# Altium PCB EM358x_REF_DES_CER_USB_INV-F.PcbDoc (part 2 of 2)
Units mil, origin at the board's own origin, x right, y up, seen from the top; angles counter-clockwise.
Board outline 2135 x 955 mil, 4 copper layers (Top Layer, Gnd Layer 2, Power Layer 3, Bottom Layer), stack 61.6 mil thick; 69 components, 52 nets, 241 pads, 167 vias.
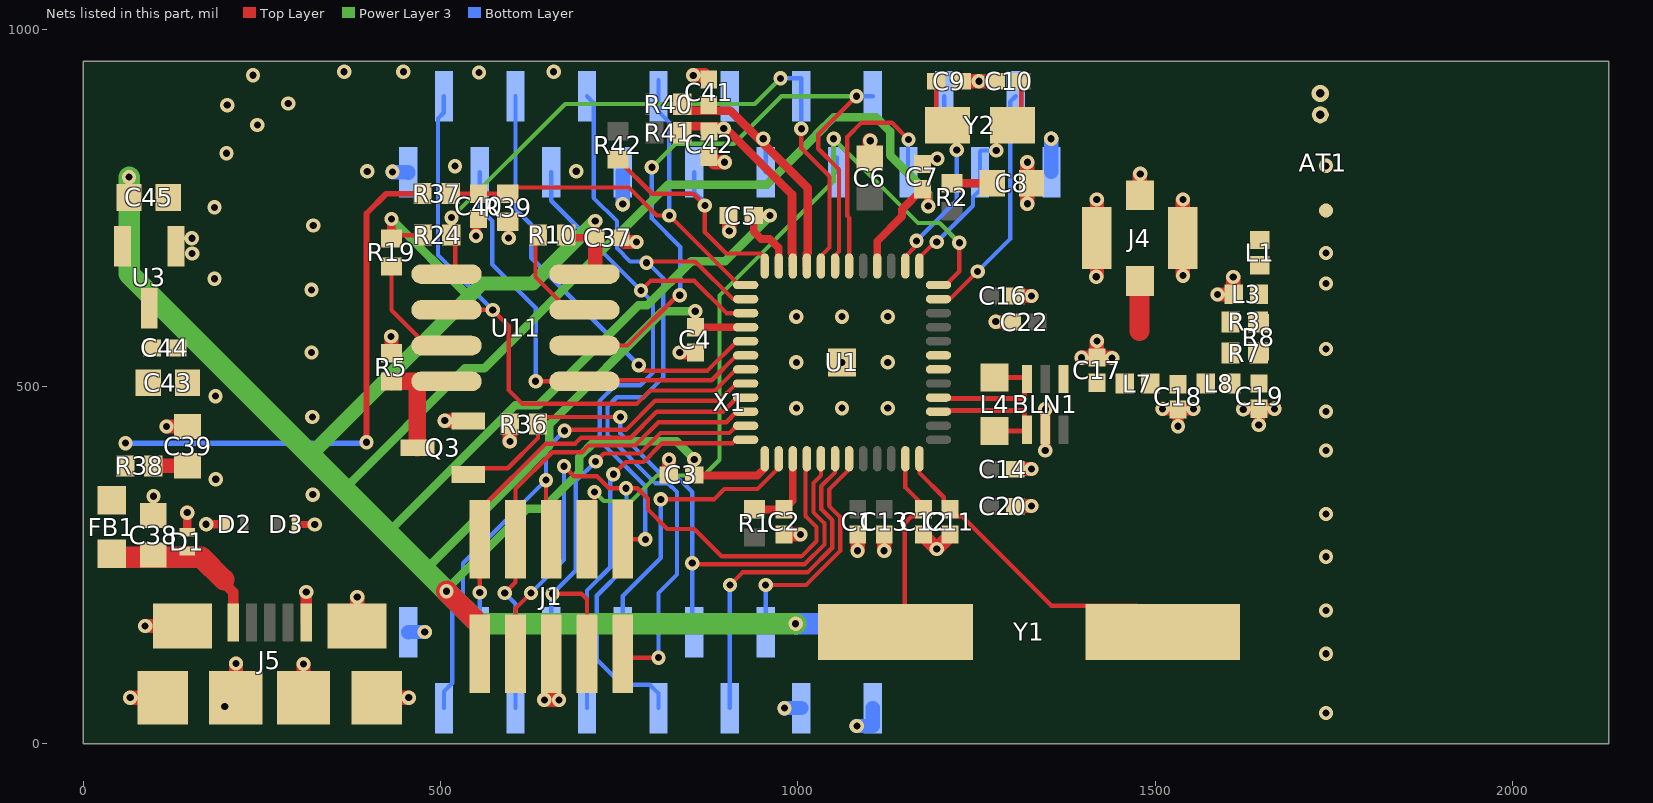
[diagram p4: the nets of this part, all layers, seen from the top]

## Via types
v1: diameter 20, hole 10, Top Layer to Bottom Layer, 166 vias
v2: diameter 24, hole 12, Top Layer to Bottom Layer, 1 vias

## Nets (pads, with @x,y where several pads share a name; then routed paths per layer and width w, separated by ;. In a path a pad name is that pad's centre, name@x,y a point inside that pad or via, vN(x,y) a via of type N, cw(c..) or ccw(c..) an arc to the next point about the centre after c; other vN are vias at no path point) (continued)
GND: AT1.2 BLN1.5 C1.2 C2.2 C3.2 C4.2 C5.2 C6.2 C7.2 C8.2 C9.2 C10.2 C11.2 C12.2 C13.2 C14.2 C16.2 C17.2 C18.2 C19.2 C20.2 C22.2 C37.2 C38.2 C39.2 C40.2 C41.2 C42.2 C43.2 C44.2 C45.2 D1.1 D2.1 D3.1 J1.5 J4.2 J4.3 J4.4 J5.5 J5.6 J5.7 J5.8 J5.9 J5.10 J5.11 L3.2 Q3.2 R5.2 R36.2 R39.2 U1.49 U3.1 X1.1 X1.13 X1.19 X1.20 X1.31 X1.33 | length 1925.6
  Top Layer w10: D3.1@296.79,306.79 296.88,306.7 v1(324.16,306.7)
  Top Layer w12: D1.1@145.63,295.5 v1(145.63,323.2) ; v1(172.03,306.92) D2.1@198.5,306.92 ; v1(549.77,710.4) 549.77,730.42 C40.2@553.4,734.05 ; R39.2@594.1,730.21 595.42,728.89 v1(595.42,707.43)
  Top Layer w14: v1@1347,468 v1(1346.5,468) 1346.41,467.91 BLN1.5@1346.41,439.13 v1(1346.41,410.09) v1@1347.5,409
  Top Layer w16: v1@312.21,213.89 v1(312.21,212.19) v1(312.21,212.19) J5.5@312.25,169.61 ; v1(1510.5,468.3) 1511.34,467.46 C18.2@1532.1,467.46 ; v1(1532.2,444.2) 1532.1,444.3 C18.2@1532.1,467.46 ; v1(1553.9,468.3) 1553.06,467.46 C18.2@1532.1,467.46 ; v1@1624.26,468.46 C19.2@1645.6,468.46 ; v1@1644.4,446.6 v1(1645.2,445.8) 1645.6,446.2 C19.2@1645.6,468.46 ; v1(1667.1,468.5) C19.2@1645.6,468.46
  Top Layer w20: v1(65.81,64.29) J5.10@111.46,64.29 ; v1(86.7,164.68) J5.11@139.02,164.68 ; v1(116.59,443.76) 116.71,443.88 C39.2@146.07,443.88 ; v1@145.41,323.42 v1(145.63,323.2) ; J5.9@213.82,64.29 v1(213.82,111.98) ; J5.8@308.31,64.29 v1(308.31,111.39) ; J5.6@383.11,164.68 383.45,165.02 v1(383.45,205.17) ; J5.7@410.67,64.29 v1(455.71,64.29) ; v1(431,569.8) 431.4,569.4 R5.2@431.4,546.07 ; v1(506,452) 538.33,452 Q3.2@538.83,451.5 ; v1(597.1,422.9) R36.2@597.1,446.9 ; J1.5@655,126 655,61.44 v1@655.26,61.18 ; v1(665.82,60.96) 665.6,61.18 v1@655.26,61.18 ; C37.2@752.06,707.87 757.89,702.04 v1(774.39,702.04) ; C3.2@819.5,376.06 C3.2@819.56,376 819.8,376.24 v1(819.8,397.7) ; v1(834.8,547.3) v1(834.8,547.3) C4.2@856.8,547.26 ; v1(853.81,935.13) 869.61,935.13 C41.2@875.5,929.24 ; C42.2@876,821.06 883.59,813.47 v1(897.7,813.47) ; C5.2@902.96,738.9 904.19,737.67 v1(904.19,717.11) ; C2.2@981,292.56 v1(1003.8,292.6) v1(1003.8,292.6) ; v1@1084,270.2 C1.2@1084,292.56 ; C6.2@1100.6,819.12 1100.6,844.3 1101.2,843.7 v1(1101.4,843.7) ; v1(1120.9,269.8) 1121,269.9 C13.2@1121,292.56 ; C12.2@1176,292.56 1176,290.8 v1(1194.4,272.4) 1213,291 C11.2@1213,292.56 ; C9.2@1229.43,926.94 v1(1253.43,926.94) C10.2@1277.43,926.94 ; v1(1277,590.5) 1277.5,590 C22.2@1299.56,590 ; C20.2@1304.44,332 1304.84,332.4 v1(1326.9,332.4) ; C16.2@1304.44,626.5 v1(1327,626.5) ; C14.2@1304.64,384.2 v1(1326.9,384.2) ; v1(1321.3,755.4) C8.2@1321.3,778.18 ; v1(1321.3,813.5) C8.2@1321.3,778.18 ; C8.2@1327.12,784 C8.2@1321.3,778.18 ; v1@1397.44,540.34 C17.2@1418.5,540.34 ; v1@1418.5,563 C17.2@1418.5,540.34 ; v1@1418.66,654.36 J4.3@1418.66,707.4 v1@1418.66,761.34 ; v1@1439.06,540.34 C17.2@1418.5,540.34 ; J4.4@1478.7,767.44 v1@1478.7,796.8 ; v1(1510.5,468.3) v1@1510.66,468.46 ; v1@1538.74,655.36 J4.2@1538.74,707.4 v1@1538.74,761.04 ; J4.2@1539.8,688.6 1548.9,697.7 J4.2@1548.86,697.74 ; v1(1587.3,628.4) 1608.68,628.4 1609.4,629.12 v1(1609.4,652.9) ; L3.2@1607.7,627.42 1608.76,626.36 1609.76,626.36 L3.2@1609.76,626.56 ; L3.2@1609.56,626.76 L3.2@1609.76,626.56 ; L3.2@1609.96,626.36 L3.2@1609.76,626.56 ; v1(1667.1,468.5) v1(1667.1,468.5) ; v1@655.26,61.18 655.48,60.96 645.58,60.96 v1(645.36,61.18) v1@655.26,61.18
  Bottom Layer w20: v1(432.73,800.16) 433.19,799.7 X1.19@455,799.7 454.6,799.3 X1.19@455.06,798.84 ; X1.20@455,156 455.33,156.33 v1(478.05,156.33) ; v1(755,754.9) X1.13@755,799.7 ; v1(981.52,49.63) 981.59,49.7 X1.31@1005,49.7 ; v1(1082.72,24.77) 1104.83,24.77 1105,24.94 X1.33@1105,49.7 ; X1.1@1354.6,800.1 v1(1354.6,846.5)
  other v1: 1739.2,42.9 198.1,52 1739.2,125.8 1739.2,186.2 1739.2,261.4 1083.6,269.8 1739.2,321.3 98.4,346.2 321.3,348.4 185.5,370 1739.2,410.2 320.7,457.1 1739.2,464.7 1623.5,467.7 997.98,469.48 1062,469.48 1126.02,469.48 185.2,486.3 997.98,533.5 1062,533.5 1126.02,533.5 1397,539.9 1439.9,539.5 319.5,547.2 1739.2,552.3 1418.8,563.3 997.98,597.52 1062,597.52 1126.02,597.52 319.5,635 1739.2,644 183.7,650.6 1417.6,653.3 1539.2,654.9 152.45,685.98 1739.2,686.5 152.12,707.21 321.9,725.1 183.7,750.4 1418.5,761.5 1539.2,761.5 1479.2,797.3 397.6,800.8 690,801 520.2,808.1 1739.2,808.5 1195.14,818.42 200.5,826.1 243.8,865.7 201.7,893.5 287,895.8 237.7,935.4 553.9,939.1 365.2,940.3 448.1,940.3 658.4,940.3
  other v2: 1731.2,910
JCLK: J1.6 U1.32 X1.21 | length 825
  Top Layer w6: v1(647.67,368.74) 647.67,293.33 J1.6@655,286 ; v1(673.52,437.82) 674.73,439.03 759.72,439.03 800.39,479.7 889.8,479.7 914.07,503.97 U1.32@927.16,503.97
  Bottom Layer w6: X1.21@505,49.7 505,73.06 516.61,84.66 516.33,84.94 516.33,188.78 531.4,203.85 531.4,252.47 v1(647.67,368.74) 647.67,411.97 v1(673.52,437.82)
NetAT1_1: AT1.1 L1.2
NetBLN1_1: BLN1.1 C17.1 L7.1
NetC2_1: C2.1 R1.2 U1.39 | length 117.1
  Top Layer w11: R1.2@939.7,327.77 980.77,327.77 C2.1@981,328 993,340 993,398.56 U1.39@993.1,398.66
NetC8_1: C8.1 R2.2 | length 56.2
  Top Layer w12: R2.2@1216,784.37 1271.63,784.37 C8.1@1272,784
NetC18_1: C18.1 L7.2 L8.1
NetC19_1: C19.1 L8.2 R7.1 R8.1
NetC38_1: C38.1 D1.2 FB1.1 J5.1 | length 211.8
  Top Layer w15: 194.81,226.79 209.88,211.72 J5.1@209.88,169.61
  Top Layer w30: 61.85,260.79 165.24,260.79 197.03,229.01
NetC39_1: C39.1 R38.1 | length 48
  Top Layer w20: R38.1@98.11,388.76 C39.1@146.07,388.76
NetJ4_1: J4.1 R3.2 R7.2 | length 70
  Top Layer w28: 1477.9,577.4 J4.1@1477.9,647.36
NetL1_1: L1.1 L3.1 R3.1 R8.2
NRESET: J1.8 U1.12 X1.7 | length 1164.9
  Top Layer w6: J1.8@705,286 715.54,296.54 v1(715.54,352.24) ; U1.12@1196.84,641.77 1207.07,641.77 1226.1,660.8 v1(1226.1,701)
  Power Layer 3 w6: v1(715.54,352.24) 728.37,339.41 767.22,339.41 803.01,375.2 868.36,375.2 890.5,397.34 890.5,627.19 1050.2,786.89 v1(1050.2,846.5) 1168.2,728.5 1198.6,728.5 v1(1226.1,701)
  Bottom Layer w6: v1(1050.2,846.5) 1049.2,845.5 1049.2,814.4 1055,820.2 X1.7@1055,799.7
NSF_GND: Q3.3 R5.1 U11.4 | length 170.2
  Top Layer w25: R5.1@431.4,506.7 431.7,507 U11.4@508.54,507 ; Q3.3@467.57,414.1 U11.4@467.57,507
NSF_HOLD: R10.1 U11.7 | length 169.7
  Top Layer w6: R10.1@627.13,714.11 R10.1@627.13,723 ; R10.1@633,713.05 R10.1@634.06,714.11 ; R10.1@636.57,711.94 633,708.37 633,653.15 679.15,607 U11.7@712.96,607
NSF_WP: R19.1 U11.3 | length 170.3
  Top Layer w6: R19.1@431.4,667.63 431.4,606.5 480.9,557 U11.3@520.04,557
OSCA: C11.1 U1.48 Y1.1 | length 458.7
  Top Layer w6: U1.48@1170.27,398.66 1170.27,378.73 1204.2,344.8 1204.2,336.8 C11.1@1213,328 1213.7,327.3 1218.4,327.3 1218.4,324.76 1224.95,318.2 1229.64,318.2 1354.77,193.07 1474,193.07 Y1.1@1510.74,156.33
OSCB: C12.1 U1.47 Y1.2 | length 277.3
  Top Layer w6: Y1.2@1136.72,156.33 1149.6,169.21 1149.6,308.44 1159.36,318.2 1163.5,318.2 C12.1@1173.5,328.2 ; U1.47@1150.58,398.66 1150.58,358.52 C12.1@1176,333.1 ; C12.1@1167.9,328.2 C12.1@1173.5,328.2 ; C12.1@1176,328 1175.8,328.2 C12.1@1173.5,328.2 ; C12.1@1176,330.7 C12.1@1173.5,328.2
PA01_D_N: C41.1 R40.2 U1.21 X1.9 | length 398.8
  Top Layer w12: R40.2@838.37,894.75 838.37,885.76 875.5,885.76 905.71,885.76 948.34,843.14 v1@948.59,842.89 ; v1(951.7,846.5) 951.7,846 v1@948.59,842.89 ; U1.21@1012.79,668.34 1012.79,685.79 1013.9,686.9 1013.9,777.58 v1@948.59,842.89
  Top Layer w18: R40.2@838.37,895.37 R40.2@839.63,895.37 ; C41.1@875.5,891.7 C41.1@875.5,893.8
  Bottom Layer w6: v1(951.7,846.5) 956,846.5 955,845.5 X1.9@955,799.7
PA01_D_P: C42.1 R41.2 U1.22 X1.10 | length 300.6
  Top Layer w12: R41.2@838.37,854.78 847.36,863.76 876,863.76 896.5,863.76 896.6,863.76 898.13,862.23 v1@899.76,860.6 ; v1(896.5,860.6) v1@899.76,860.6 ; U1.22@993.1,668.34 993.1,685.5 991.9,686.7 991.9,768.47 v1@899.76,860.6
PA2: R42.2 U1.24 X1.11 | length 348.8
  Top Layer w6: R42.2@748.21,817.44 796.29,769.36 853.64,769.36 v1(870,753) 870,715.66 899.86,685.8 947.8,685.8 953.73,679.87 U1.24@953.73,668.34
  Bottom Layer w6: X1.11@855,799.7 855,772 870,757 v1(870,753)
PA3: C40.1 R37.2 R39.1 U1.25 X1.12 | length 668.4
  Top Layer w6: R37.2@514.34,769.58 514.43,769.49 C40.1@553.4,769.49 594.01,769.49 R39.1@594.1,769.58 602.71,778.19 763.69,778.19 802.78,739.1 v1(820.3,739.1) 917.63,641.77 U1.25@927.16,641.77
  Bottom Layer w6: X1.12@805,928.16 X1.12@805,906 805,884.39 820.3,869.09 v1(820.3,739.1)
PA4: J1.9 U1.26 X1.14 | length 1162.8
  Top Layer w6: J1.9@755,114.5 760.8,120.3 v1(805.1,120.3) ; v1(788.25,673) 788.25,674.75 788.2,674.8 856.6,674.8 909.32,622.08 U1.26@914.42,622.08
  Bottom Layer w6: X1.14@705,906 714.33,896.67 714.33,763.75 746.89,731.19 746.89,693.35 765.44,674.8 v1@788.2,674.8 ; v1(788.25,673) 788.25,674.75 v1@788.2,674.8 ; v1(805.1,120.3) 805.1,210.8 830.93,236.63 830.93,352.13 818.86,364.2 801.04,364.2 733.73,431.51 733.73,471.53 746.8,484.6 784,484.6 811.6,512.2 811.6,651.4 v1@788.2,674.8
PA5: J1.10 U1.27 X1.15 | length 853.4
  Top Layer w6: J1.10@755,286 755.2,285.8 v1(786.71,285.8) ; v1(780.5,634.2) 793.9,647.6 855.1,647.6 900.3,602.4 U1.27@927.16,602.4
  Bottom Layer w6: X1.15@655,799.7 655,759.7 v1(780.5,634.2) 797.5,617.2 797.5,519.3 779.7,501.5 745,501.5 722.73,479.23 722.73,424.14 786.71,360.16 v1(786.71,285.8)
PA6: U1.29 X1.16 | length 617.7
  Top Layer w6: v1(777.4,529.6) 785.03,521.97 873.79,521.97 914.85,563.03 U1.29@927.16,563.03
  Bottom Layer w6: X1.16@605,906 605,748.12 627.13,725.99 627.13,679.87 v1(777.4,529.6)
PA7: U1.18 X1.5 | length 331
  Top Layer w6: U1.18@1071.84,668.34 1072,668.5 1072,735.6 1069.4,738.2 1069.4,849.32 1089.08,869 1131.5,869 v1(1155.1,845.4)
  Bottom Layer w6: X1.5@1154.2,800.5 1154.2,844.5 v1(1155.1,845.4)
PB0: U1.36 X1.25 | length 573.9
  Top Layer w6: v1(741.94,376.88) 759.21,394.15 784.03,394.15 810.18,420.3 908.6,420.3 913.53,425.23 U1.36@927.16,425.23 ; 785.3,395.1 803.8,413.6
  Bottom Layer w6: X1.25@705,49.7 705,214.21 737.63,246.84 737.63,372.57 v1(741.94,376.88)
PB1: U1.30 U11.5 X1.17 | length 634.1
  Top Layer w6: v1(633.2,507) U11.5@701.46,507 703.06,508.6 879.6,508.6 914.34,543.34 U1.30@927.16,543.34
  Bottom Layer w6: X1.17@555,799.7 555,748.84 572.54,731.3 572.54,670.66 633.2,610 v1(633.2,507)
PB2: U1.31 U11.2 X1.18 | length 880.1
  Top Layer w6: U11.2@508.54,607 573.1,607 v1(573.2,606.9) 595.4,584.7 595.4,494.9 614.9,475.4 774.5,475.4 793.2,494.1 884,494.1 913.56,523.66 U1.31@927.16,523.66
  Bottom Layer w6: X1.18@505,906 504.5,905.5 504.5,882.8 496.5,874.8 496.5,683.6 v1(573.2,606.9)
PB3: U1.19 U11.6 X1.6 | length 982.8
  Top Layer w6: U11.6@701.46,557 761.6,557 832.1,627.5 v1(834.9,627.5) ; U1.19@1052.16,668.34 1052.16,683.16 1057.6,688.6 1057.6,803.6 1028.7,832.5 1028.7,852.6 v1(1082.1,906)
  Power Layer 3 w6: v1(795.8,806.65) 828.69,839.54 910.59,839.54 977.05,906 v1(1082.1,906)
  Bottom Layer w6: v1(795.8,806.65) 795.8,734.8 835.5,695.1 835.5,628.1 v1(834.9,627.5) ; v1(1082.1,906) X1.6@1105,906
PB4: R24.1 U1.20 U11.1 X1.8 | length 966
  Top Layer w6: R24.1@524,718.7 520.5,718.7 520.5,657.46 520.04,657 U11.1@550,657 ; v1(1005,860.5) 1005,833.34 1044.5,793.84 1044.5,694.4 1032.47,682.37 U1.20@1032.47,668.34
  Power Layer 3 w6: v1(515.56,736.03) 674.51,894.98 939.83,894.98 v1(975.85,931) ; v1@1001,854.29 1001,864.5 v1(1005,860.5)
  Bottom Layer w6: v1@975.47,930.62 v1(975.85,931) 1005,931 X1.8@1005,906 v1(1005,860.5)
PB5: U1.43 X1.30 | length 337
  Top Layer w6: v1(955,222) 1011.69,222 1059.3,269.61 1059.3,317.31 1043.9,332.71 1043.9,355.72 1071.84,383.66 U1.43@1071.84,398.66
  Bottom Layer w6: X1.30@955,156 v1(955,222)
PB6: U1.42 X1.29 | length 475.9
  Top Layer w6: v1(905.3,222.1) 923.2,240 1014.13,240 1048.3,274.17 1048.3,312.76 1032.9,328.16 1032.9,360.28 1052.16,379.53 U1.42@1052.16,398.66
  Bottom Layer w6: X1.29@905,49.7 905,221.8 v1(905.3,222.1)
PB7: Q3.1 R36.1 U1.41 X1.28 | length 940.2
  Top Layer w6: Q3.1@538.83,376.7 547.53,385.4 594.15,385.4 636.37,427.62 R36.1@636.37,447 646.55,457.18 v1(751.73,457.18) ; v1(852.4,252.5) 853.9,251 1009.58,251 1037.3,278.72 1037.3,308.2 1021.9,323.6 1021.9,364.83 1032.47,375.4 U1.41@1032.47,398.66
  Bottom Layer w6: v1(751.73,457.18) 751.73,433.95 810.48,375.2 829.12,375.2 852.4,351.92 v1(852.4,252.5) 852.4,158.6 X1.28@855,156
PC0: J1.3 U1.40 X1.27 | length 1219.6
  Top Layer w6: J1.3@605,126 605,189.12 v1(626.66,210.78) ; v1(672.97,388.21) 687.05,374.13 719.11,374.13 735.83,357.41 v1(759.76,357.41) 775.49,357.41 790.27,342.63 790.27,327.45 817.4,300.32 855.24,300.32 893.56,262 1005.02,262 1026.3,283.28 1026.3,302.9 1010.9,318.3 1010.9,396.77 U1.40@1012.79,398.66
  Bottom Layer w6: v1(626.66,210.78) 672.97,257.09 v1(672.97,388.21) ; v1(759.76,357.41) 760.3,356.87 760.3,248.5 718.8,207 718.8,117.7 754.3,82.2 792.8,82.2 805,70 X1.27@805,49.7
PC1: U1.38 X1.26 | length 390.4
  Top Layer w6: v1(808.27,341.79) 882.63,341.79 897.03,356.19 943.68,356.19 976.49,389 973.42,389 U1.38@973.42,398.66
  Bottom Layer w6: X1.26@755,174.1 755,206.57 808.4,259.97 808.4,341.66 v1(808.27,341.79)
PC2: J1.2 U1.33 X1.22 | length 608.6
  Top Layer w6: v1(554.94,211.33) 555,211.39 J1.2@555,286 555,327.33 647.49,419.82 688.41,419.82 696.62,428.03 766.23,428.03 802.5,464.3 895.3,464.3 915.29,484.29 U1.33@927.16,484.29
  Bottom Layer w6: v1(554.94,211.33) 554.94,156.06 X1.22@555,156
PC3: J1.4 U1.34 X1.23 | length 686.1
  Top Layer w6: v1(589.92,210.78) 605,225.86 J1.4@605,286 605,356.32 656.47,407.79 697.94,407.79 707.18,417.03 772.43,417.03 805.1,449.7 899.8,449.7 914.7,464.6 U1.34@927.16,464.6
  Bottom Layer w6: v1(589.92,210.78) 605,195.7 X1.23@605,49.7
PC4: J1.7 U1.35 X1.24 | length 622.6
  Top Layer w6: v1(656.8,209.68) 697.28,209.68 705,201.96 J1.7@705,126 ; v1(717.19,394.7) 728.52,406.03 779.33,406.03 808,434.7 904.4,434.7 914.62,444.92 U1.35@927.16,444.92
  Bottom Layer w6: X1.24@655,156 655,207.88 v1(656.8,209.68) 689.14,242.02 689.14,366.65 v1(717.19,394.7)
PC5: U1.11 X1.2 | length 338.2
  Top Layer w6: U1.11@1196.84,622.08 1213.08,622.08 v1(1251.7,660.7)
  Bottom Layer w6: v1(1251.7,660.7) 1297.2,706.2 1297.2,898.2 X1.2@1305,906
PC6: C10.1 U1.13 X1.3 Y2.1 | length 358.9
  Top Layer w6: U1.13@1170.27,668.34 1170.27,680.27 1191.9,701.9 v1(1194.4,701.9) ; v1(1277.86,829.86) 1277.86,843.09 Y2.1@1300.21,865.44 ; Y2.1@1278.43,864.94 1279.93,866.44 1310.43,866.44 1312.87,868.88 C10.1@1312.87,926.94
  Bottom Layer w6: v1(1194.4,701.9) 1245.1,752.6 1245.1,764.86 1255,774.76 X1.3@1255,799.7 1255,828.12 1256.74,829.86 v1(1277.86,829.86)
PC7: C9.1 U1.14 X1.4 Y2.2 | length 368.5
  Top Layer w6: U1.14@1150.58,668.34 1150.58,681.88 1166.1,697.4 v1(1166.1,703.6) ; C9.1@1193.99,926.94 1193.99,882.1 Y2.2@1228.63,847.46
  Bottom Layer w6: v1(1166.1,703.6) 1222.42,759.92 v1(1222.42,830.63) 1222.42,865.06 1205,882.48 X1.4@1205,906
RF_N: BLN1.3 L4.1 U1.4 | length 195.8
  Top Layer w7: U1.4@1196.84,484.29 1198.13,483 1317.5,483 1317.5,506.68 BLN1.3@1320.82,510 1318.52,512.3 L4.1@1275.5,512.3
RF_P: BLN1.4 L4.2 U1.3 | length 198.2
  Top Layer w7: U1.3@1184.84,466.6 U1.3@1186.79,464.66 ; U1.3@1196.84,464.6 1198.24,466 1317.5,466 1317.5,442.45 BLN1.4@1320.82,439.13 1319.18,437.5 L4.2@1275.5,437.5
TX_ALT_N: U1.7
TX_ALT_P: U1.6
VBRD: C3.1 C4.1 C5.1 C7.1 C37.1 C45.1 J1.1 R10.2 R19.2 R24.2 U1.16 U1.23 U1.28 U1.37 U3.2 U11.8 X1.32 | length 5646
  Top Layer w6: R19.2@441,711.5 R24.2@475.63,711.5 R24.2@481.13,711.5
  Top Layer w8: R19.2@430.07,705.67 R19.2@431.4,707
  Top Layer w10: R10.2@675.94,711.94 680.01,707.87 716.42,707.87 C37.1@716.62,707.87
  Top Layer w11: v1(856.6,605.1) 856.6,582.9 C4.1@856.8,582.7 U1.28@927.16,582.71 ; C3.1@857.65,378.65 861.2,375.1 943.5,375.1 953.73,385.33 U1.37@953.73,398.66 ; C5.1@938.4,738.9 938.4,716.6 948.8,706.2 960.7,706.2 973.42,693.48 U1.23@973.42,668.34 ; C5.1@938.6,739.1 v1(960.9,739.1) ; U1.16@1111.21,668.34 1111.21,703.05 1146,737.83 1146,747.46 C7.1@1174.3,775.76 1182.5,767.56 v1(1182.5,752.1)
  Top Layer w12: R19.2@431.4,707 v1(431.4,734.17) ; C37.1@716.62,707.87 v1(716.62,731.21)
  Top Layer w20: U11.8@701.46,657 716.42,657 C37.1@716.42,707.87
  Top Layer w25: J1.1@547.36,174.37 555,166.73 J1.1@555,126
  Top Layer w30: v1(508.53,213.2) J1.1@547.36,174.37
  Power Layer 3 w12: 368.32,359.12 534.36,525.16 561.45,525.16 818.29,782 956.2,782 1026,851.8 1026,852 1050.72,876.72 1109.12,876.72 1129.14,856.7 1129.14,823.37 1182.5,770.01 v1(1182.5,752.1) ; 426.57,295.48 604.44,473.35 636.78,473.35 776.63,613.2 789.2,613.2 851.09,675.09 898.23,675.09 960.9,737.76 v1(960.9,739.1) ; v1(431.4,734.17) 538.88,626.69 540.97,626.69 ; 478.32,242.62 652.52,416.82 652.52,446.52 811.1,605.1 v1(856.6,605.1) ; v1(508.53,213.2) 508.53,215.74 621.16,328.37 642.83,328.37 693.97,379.51 693.97,401.18 715.99,423.2 830.36,423.2 855.1,398.46 v1(855.1,397.8)
  Power Layer 3 w20: 317.51,404.22 318.5,404.22 540.97,626.69 558.02,643.74 629.15,643.74 v1(716.62,731.21)
  Power Layer 3 w30: v1(64.23,792.68) 64.23,657.5 317.51,404.22 v1(508.53,213.2) 554.07,167.66 v1(997.03,167.66)
  Bottom Layer w20: X1.32@1043.34,167.66 X1.32@1055,156
  Bottom Layer w30: v1(997.03,167.66) X1.32@1043.34,167.66
VBUS: C43.1 C44.1 FB1.2 R37.1 R38.2 U3.3 | length 748
  Top Layer w8: v1(396.43,421.65) 396.43,741.86 424.15,769.58 R37.1@474.97,769.58
  Bottom Layer w8: v1(59.28,420.44) 59.46,420.26 395.04,420.26 v1(396.43,421.65)
pads on no net: BLN1.6 J5.4 U1.9

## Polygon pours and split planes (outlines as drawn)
GND on Gnd Layer 2 "GND_2" (solid, remove dead copper, pour order 17): 5,5 5,950 2135,950 2135,5
GND on Bottom Layer "GND_4" (solid, remove dead copper, pour order 18): 5,5 5,950 2135,950 2135,5
GND on Top Layer "USB Shield" (solid, pour order 4): 173,341 366,341 366,739 415,788 708,788 708,950 173,950

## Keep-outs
Keep-Out Layer:
  text ".Layer_Name" at 4355,-2681 h70

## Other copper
Top Layer:
  region net NetC19_1: 1631.4,490.05 1631.4,561.35 1658.7,561.35 1658.7,490.05
  region net NetAT1_1: 1632.4,732.9 1749.5,732.9 1749.5,760.6 1632.4,760.6
  region net GND: 1749.2,9 1744.2,4 1719.1,4 1714.6,8.5 1714.6,700.1 1720.2,705.7 1744.4,705.7 1749.2,700.9
  region net GND: 1713.2,792.1 1717.5,787.8 1745,787.8 1749.2,792 1749.2,946.8 1745,951 1717.6,951 1713.2,946.6
  region net NetBLN1_1: 1470.4,517.7 1470.4,490.1 1365.3,490.1 1365.3,517.7
  region net NetC18_1: 1480.3,517.7 1583.9,517.7 1583.9,490.1 1480.3,490.1
  region net NetC19_1: 1593.8,517.7 1658.4,517.7 1658.4,490.1 1593.8,490.1
  region net NetJ4_1: 1592.8,604.9 1618.4,604.9 1618.4,531.8 1592.8,531.8
  region net NetJ4_1: 1491.9,582 1618.85,582 1618.85,554.2 1479.55,554.2 1459.25,574.4 1459.3,634.4 1491.9,634.4
  region net NetL1_1: 1632.58,575.3 1661.06,575.3 1660.99,682.75 1632.62,682.75
  region net NetAT1_1: 1661,692.3 1661,760.1 1632.4,760.1 1632.4,692.3
  region net GND: 101.4,783 101.4,667.1 119,667.1 119,541.6 128.2,541.6 128.6,542 128.6,486 163.3,486 164.2,486.9 164.2,783
  region net VBUS: 59.7,320.7 59.7,360.4 71.7,372.4 71.8,485.6 109.2,485.6 109.2,565.5 104.3,565.5 104.3,638.3 5,638.3 5,320.7
  region net VBRD: 81.5,667.4 81.5,812.5 82.8,813.8 164.8,813.8 164.8,950 5,950 4.8,667.4
  text ".Layer_Name" at 4355,-2681 h70
Gnd Layer 2:
  text ".Layer_Name" at 4355,-2681 h70
Power Layer 3:
  text ".Layer_Name" at 4355,-2681 h70
Bottom Layer:
  text ".Layer_Name" at 4355,-2681 h70

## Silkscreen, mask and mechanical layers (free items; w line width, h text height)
Top Overlay:
  text ".Layer_Name" at 4355,-2681 h70
Bottom Overlay:
  text ".Layer_Name" at 4355,-2681 h70
Top Paste:
  text ".Layer_Name" at 4355,-2681 h70
Bottom Paste:
  text ".Layer_Name" at 4355,-2681 h70
Top Solder:
  text ".Layer_Name" at 4355,-2681 h70
Bottom Solder:
  text ".Layer_Name" at 4355,-2681 h70
Drill Guide:
  text ".Layer_Name" at 4355,-2681 h70
M1 Top Assembly:
  text ".Layer_Name" at 4355,-2681 h70
M2 Bottom Assembly:
  text ".Layer_Name" at 4355,-2681 h70
M7 Board Outline:
  the board outline again, w1
M13 Top 3D:
  text ".Layer_Name" at 4355,-2681 h70
M16 Sheet Border:
  lines w5: -1995,-1085 -1795,-1085 ; -1995,787 -1795,787 ; -1995,2667 -1795,2667 ; -1795,-2245 3043,-2245 ; -1794.6,-2023.8 3043.4,-2023.8 ; 381,-2961 381,-2761 ; 381,4339 381,4539 ; 1405,-2761 3043,-2761 3043,-1561 4305,-1561 ; 2753,-2961 2753,-2761 ; 2753,4339 2753,4539 ; 2805,-2761 7305,-2761 ; 4303,-2461 7305,-2461 ; 4303,-2161 7305,-2161 ; 4303,-1861 7308,-1861 ; 4305,-2761 4305,-2161 4305,-1561 ; 5130,-2961 5130,-2761 ; 5130,4339 5130,4539 ; 6405,-2761 6405,-2161 ; 7305,-1085 7505,-1085 ; 7305,787 7505,787 ; 7305,2667 7505,2667 ; 4305,-1561 7305,-1561 7305,-2761 ; 7305,-2761 7305,4339 -1795,4339 -1795,-2761 7305,-2761 ; -1995,-2961 7505,-2961 7505,4539 -1995,4539 -1995,-2961
  text "1" at -822.66,4404 h70
  text "2" at 1535.35,4404 h70
  text "3" at 3912,4404 h70
  text "4" at 6287.35,4404 h70
  text "A" at -1920,3514 h70
  text "A" at 7375,3514 h70
  text "B" at -1920,1638 h70
  text "B" at 7375,1638 h70
  text "C" at -1920,-238 h70
  text "C" at 7375,-238 h70
  text "TITLE:" at 4355,-1661 h45
  text ".Title" at 4355,-1781 h70
  text "FILE NAME:" at 4355,-1961 h45
  text ".Pcb_File_Name_No_Path" at 4355,-2081 h70
  text "D" at -1920,-2110 h70
  text "D" at 7375,-2110 h70
  text "MCU & Wireless Division Simplicity Support Group" at -1092.5,-2171.6 h70
  text "Board NO.:" at 4355,-2261 h45
  text "REV:" at 6455,-2261 h45
  text ".Company Address 1" at 3100,-2281 h70
  text "The information in this document is subject to change without notice. The statements, configurations," at -1700,-2361 h45
  text ".Company Address 2" at 3100,-2381 h70
  text ".Board Rev" at 6455,-2381 h70
  text ".Board No" at 4355,-2401.5 h70
  text "technical data and recommendations in this  document are believed to be accurate and reliable, but are" at -1700,-2436 h45
  text ".Company Address 3" at 3100,-2481 h70
  text "presented without express or implied warranty. The information in this document is  the proprietary and" at -1700,-2511 h45
  text "Layer:" at 4355,-2561 h45
  text "DATE:" at 6455,-2561 h45
  text ".Company Web Site" at 3100,-2581 h70
  text "confidential property of Silicon Labs and is privileged. No part of the drawing or information may be" at -1700,-2586 h45
  text "duplicated or otherwise  used without the express permission of Silicon Labs." at -1700,-2661 h45
  text ".Company Tel" at 3100,-2681 h70
  text ".Print_Date" at 6455,-2681 h70
  text "1" at -822.66,-2896 h70
  text "2" at 1535.35,-2896 h70
  text "3" at 3912,-2896 h70
  text "4" at 6287.35,-2896 h70
  text ".Company Design Group" at 1154.2,-6875.6 h70
Drill Drawing:
  drawing of 475 lines, arcs and shapes, not listed
  text "Fabrication Notes:" at -1708.9,4193.2 h70
  text "1. All dimensions in inches.  Tolerance = +/- 0.005\" unless noted otherwise" at -1708.9,4093.2 h45
  text "2. All materials: laminates, resins, metallizations and soldermask to be compliant to EU RoHS directive 2002/95/EC IAW SP-12509-01." at -1708.9,4018.2 h45
  text "3. 370 HR FR-4 or similar grade glass epoxy." at -1708.9,3943.2 h45
  text "4. Tg > 170 degrees celcius, glass transition temperature." at -1708.9,3868.2 h45
  text "5. TD > 350 degrees celcius, thermal decomposition." at -1708.9,3793.2 h45
  text "6. Er = 4.0 +/- 5% @ 2.5GHz." at -1708.9,3718.2 h45
  text "7. Minimum flammability rating UL94V-0, maximum dissipation factor 0.025." at -1708.9,3643.2 h45
  text "8. Adjust prepreg for 0.062\", +/- 0.003\" finished thickness measured over soldermask." at -1708.9,3568.2 h45
  text "9. Copper thickness 0.0014\", (1 oz)." at -1708.9,3493.2 h45
  text "10. Hole size tolerance = +/- 0.003\" unless noted otherwise." at -1708.9,3418.2 h45
  text "11. Hole centers and pad centers to be concentric within 0.002\"." at -1708.9,3343.2 h45
  text "12. Drill chart dimensions are drill sizes and not finished hole sizes." at -1708.9,3268.2 h45
  text "13. Finish - immersion gold over nickel.  No exposed bare copper permitted." at -1708.9,3193.2 h45
  text "14. Thieving not allowed on layer 1." at -1708.9,3118.2 h45
  text "15. Solder mask over bare copper, LPI class 2 gen. industrial registration +/- 0.004\"." at -1708.9,3043.2 h45
  text "16. No coverage on solder pads permitted." at -1708.9,2968.2 h45
  text "17. Refer to soldermask gerbers for tenting of vias." at -1708.9,2893.2 h45
  text "18. White silkscreen legend over red soldermask - both sides." at -1708.9,2818.2 h45
  text "19. Manufacturer icons not permitted on the silkscreen top layer." at -1708.9,2743.2 h45
  text "20. PCB serialization/panel placement ID on silkscreen bottom." at -1708.9,2668.2 h45
  text "21. Full electrical test against IPC-356A netlist." at -1708.9,2593.2 h45
  text "Layer" at 2650.6,2297.8 h60
  text "Name" at 3060.51,2297.8 h60
  text "Material" at 3990.26,2297.8 h60
  text "Thickness" at 4850.02,2297.8 h60
  text "Constant" at 5499.86,2297.8 h60
  text "Board Layer Stack" at 6069.72,2297.8 h60
  text "1" at 2650.6,2177.8 h60
  text "Top Paste" at 3060.51,2177.8 h60
  text "2" at 2650.6,2057.8 h60
  text "Top Overlay" at 3060.51,2057.8 h60
  text "3" at 2650.6,1937.8 h60
  text "Top Solder" at 3060.51,1937.8 h60
  text "Solder Resist" at 3990.26,1937.8 h60
  text "0.40mil" at 4850.02,1937.8 h60
  text "3.5" at 5499.86,1937.8 h60
  text "4" at 2650.6,1817.8 h60
  text "Top Layer" at 3060.51,1817.8 h60
  text "Copper" at 3990.26,1817.8 h60
  text "1.40mil" at 4850.02,1817.8 h60
  text "5" at 2650.6,1697.8 h60
  text "Dielectric1" at 3060.51,1697.8 h60
  text "HR370" at 3990.26,1697.8 h60
  text "16.00mil" at 4850.02,1697.8 h60
  text "3.9" at 5499.86,1697.8 h60
  text "6" at 2650.6,1577.8 h60
  text "Gnd Layer 2" at 3060.51,1577.8 h60
  text "Copper" at 3990.26,1577.8 h60
  text "1.40mil" at 4850.02,1577.8 h60
  text "7" at 2650.6,1457.8 h60
  text "Dielectric2" at 3060.51,1457.8 h60
  text "HR370" at 3990.26,1457.8 h60
  text "24.00mil" at 4850.02,1457.8 h60
  text "3.9" at 5499.86,1457.8 h60
  text "8" at 2650.6,1337.8 h60
  text "Power Layer 3" at 3060.51,1337.8 h60
  text "Copper" at 3990.26,1337.8 h60
  text "1.40mil" at 4850.02,1337.8 h60
  text "9" at 2650.6,1217.8 h60
  text "Dielectric3" at 3060.51,1217.8 h60
  text "HR370" at 3990.26,1217.8 h60
  text "16.00mil" at 4850.02,1217.8 h60
  text "3.9" at 5499.86,1217.8 h60
  text "10" at 2650.6,1097.8 h60
  text "Bottom Layer" at 3060.51,1097.8 h60
  text "Copper" at 3990.26,1097.8 h60
  text "1.40mil" at 4850.02,1097.8 h60
  text "11" at 2650.6,977.8 h60
  text "Bottom Solder" at 3060.51,977.8 h60
  text "Solder Resist" at 3990.26,977.8 h60
  text "0.40mil" at 4850.02,977.8 h60
  text "3.5" at 5499.86,977.8 h60
  text "12" at 2650.6,857.8 h60
  text "Bottom Overlay" at 3060.51,857.8 h60
  text "13" at 2650.6,737.8 h60
  text "Bottom Paste" at 3060.51,737.8 h60
  text "Symbol" at -46.08,-434.21 h45.12
  text "Hit Count" at 282.87,-434.21 h45.12
  text "Finished Hole Size" at 732.1,-434.21 h45.12
  text "Plated" at 1587.26,-434.21 h45.12
  text "Hole Type" at 1916.21,-434.21 h45.12
  text "2" at 282.87,-528.2 h37.6
  text "12.00mil (0.305mm)" at 732.1,-528.2 h37.6
  text "PTH" at 1587.26,-528.2 h37.6
  text "Round" at 1916.21,-528.2 h37.6
  text "166" at 282.87,-622.2 h37.6
  text "10.00mil (0.254mm)" at 732.1,-622.2 h37.6
  text "PTH" at 1587.26,-622.2 h37.6
  text "Round" at 1916.21,-622.2 h37.6
  text "168 Total" at 282.87,-716.2 h37.6
  text ".Layer_Name" at 4355,-2681 h70

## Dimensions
0,955 to 0,0 on Drill Drawing
0,955 to 2135,955 on Drill Drawing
